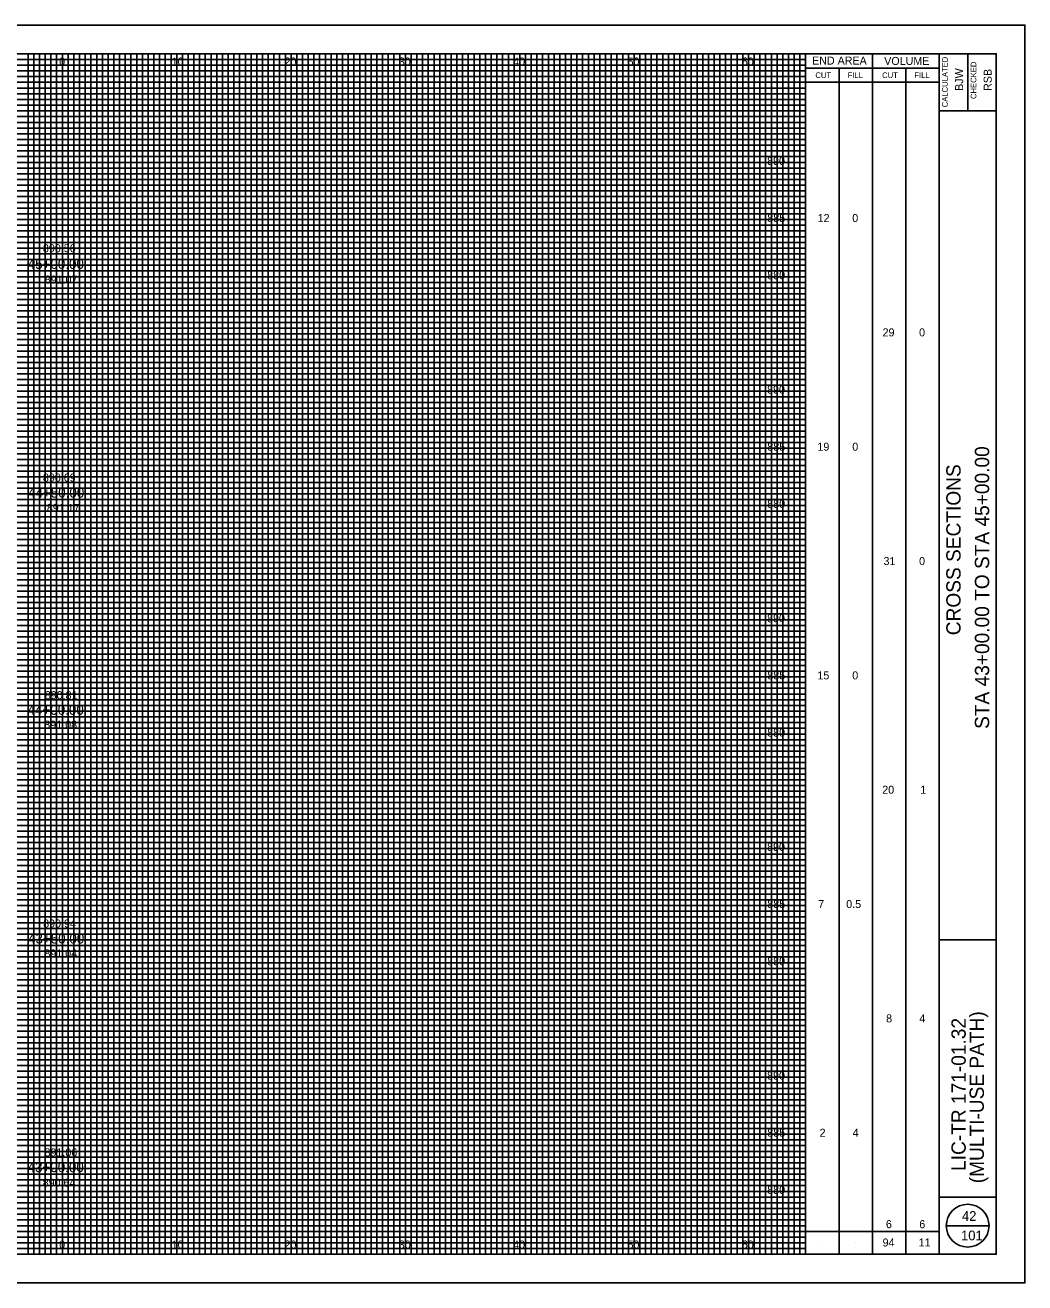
# Model space of a CAD drawing. Extents: x -10 to 160, y -2 to 2522.
# Drawn here: x 72.6 to 160, y 1607.5 to 1717.5 of the extents above; entities that cross this region are included whole.
import ezdxf

# ---------------------------------------------------------------- set-up
doc = ezdxf.new("R2010")
doc.units = 0
for name, color, linetype in [('GK_Cells', 7, 'Continuous'), ('GK_Patterns', 7, 'Continuous'), ('TX_P_10', 7, 'Continuous'), ('TX_X_10', 7, 'Continuous'), ('XS_P_Finished_Grade_Seeded', 7, 'Continuous'), ('XS_P_Pavt_Surface', 7, 'Continuous'), ('XS_P_Subgrade', 7, 'Continuous'), ('XS_X_Ground_Line', 7, 'Continuous')]:
    doc.layers.add(name, color=color, linetype=linetype)

msp = doc.modelspace()

# ---------------------------------------------------------------- linework, layer by layer
at = {"layer": 'GK_Cells'}
msp.add_lwpolyline([(-10, 1607.5), (160, 1607.5), (160, 1717.5), (-10, 1717.5)], close=True, dxfattribs=at)
at = {"layer": 'TX_P_10'}
for p, q in [((140.83, 1610), (140.83, 1715)), ((146.67, 1610), (146.67, 1715)), ((140.83, 1713.75), (152.5, 1713.75)), ((143.75, 1610), (143.75, 1713.75)), ((149.58, 1610), (149.58, 1713.75)), ((140.83, 1712.5), (152.5, 1712.5)), ((140.83, 1612), (152.5, 1612)), ((153.12, 1612.5), (156.88, 1612.5)), ((142.29, 1611), (142.29, 1611)), ((145.21, 1611), (145.21, 1611)), ((148.12, 1611), (148.12, 1611)), ((151.04, 1611), (151.04, 1611))]:
    msp.add_line(p, q, dxfattribs=at)
msp.add_circle((155, 1612.5), 1.87, dxfattribs=at)
at = {"layer": 'TX_X_10'}
for p, q in [((75.83, 1610), (75.83, 1715)), ((80.83, 1610), (80.83, 1715)), ((85.83, 1610), (85.83, 1715)), ((90.83, 1610), (90.83, 1715)), ((95.83, 1610), (95.83, 1715)), ((100.83, 1610), (100.83, 1715)), ((105.83, 1610), (105.83, 1715)), ((110.83, 1610), (110.83, 1715)), ((115.83, 1610), (115.83, 1715)), ((120.83, 1610), (120.83, 1715)), ((125.83, 1610), (125.83, 1715)), ((130.83, 1610), (130.83, 1715)), ((135.83, 1610), (135.83, 1715)), ((5.83, 1710), (140.83, 1710)), ((5.83, 1705), (140.83, 1705)), ((5.83, 1700), (140.83, 1700)), ((5.83, 1695), (140.83, 1695)), ((5.83, 1690), (140.83, 1690)), ((5.83, 1685), (140.83, 1685)), ((5.83, 1680), (140.83, 1680)), ((5.83, 1675), (140.83, 1675)), ((5.83, 1670), (140.83, 1670)), ((5.83, 1665), (140.83, 1665)), ((5.83, 1660), (140.83, 1660)), ((5.83, 1655), (140.83, 1655)), ((5.83, 1650), (140.83, 1650)), ((5.83, 1645), (140.83, 1645)), ((5.83, 1640), (140.83, 1640)), ((5.83, 1635), (140.83, 1635)), ((5.83, 1630), (140.83, 1630)), ((5.83, 1625), (140.83, 1625)), ((5.83, 1620), (140.83, 1620)), ((5.83, 1615), (140.83, 1615))]:
    msp.add_line(p, q, dxfattribs=at)
at = {"layer": 'XS_P_Pavt_Surface'}
for p, q in [((152.5, 1610), (152.5, 1715)), ((155, 1715), (155, 1710)), ((152.5, 1710), (157.5, 1710)), ((152.5, 1637.5), (157.5, 1637.5)), ((152.5, 1615), (157.5, 1615))]:
    msp.add_line(p, q, dxfattribs=at)
msp.add_lwpolyline([(0, 1715), (157.5, 1715), (157.5, 1610), (0, 1610)], close=True, dxfattribs=at)
at = {"layer": 'XS_X_Ground_Line'}
for p, q in [((72.83, 1610), (72.83, 1715)), ((73.33, 1610), (73.33, 1715)), ((73.83, 1610), (73.83, 1715)), ((74.33, 1610), (74.33, 1715)), ((74.83, 1610), (74.83, 1715)), ((75.33, 1610), (75.33, 1715)), ((76.33, 1610), (76.33, 1715)), ((76.83, 1610), (76.83, 1715)), ((77.33, 1610), (77.33, 1715)), ((77.83, 1610), (77.83, 1715)), ((78.33, 1610), (78.33, 1715)), ((78.83, 1610), (78.83, 1715)), ((79.33, 1610), (79.33, 1715)), ((79.83, 1610), (79.83, 1715)), ((80.33, 1610), (80.33, 1715)), ((81.33, 1610), (81.33, 1715)), ((81.83, 1610), (81.83, 1715)), ((82.33, 1610), (82.33, 1715)), ((82.83, 1610), (82.83, 1715)), ((83.33, 1610), (83.33, 1715)), ((83.83, 1610), (83.83, 1715)), ((84.33, 1610), (84.33, 1715)), ((84.83, 1610), (84.83, 1715)), ((85.33, 1610), (85.33, 1715)), ((86.33, 1610), (86.33, 1715)), ((86.83, 1610), (86.83, 1715)), ((87.33, 1610), (87.33, 1715)), ((87.83, 1610), (87.83, 1715)), ((88.33, 1610), (88.33, 1715)), ((88.83, 1610), (88.83, 1715)), ((89.33, 1610), (89.33, 1715)), ((89.83, 1610), (89.83, 1715)), ((90.33, 1610), (90.33, 1715)), ((91.33, 1610), (91.33, 1715)), ((91.83, 1610), (91.83, 1715)), ((92.33, 1610), (92.33, 1715)), ((92.83, 1610), (92.83, 1715)), ((93.33, 1610), (93.33, 1715)), ((93.83, 1610), (93.83, 1715)), ((94.33, 1610), (94.33, 1715)), ((94.83, 1610), (94.83, 1715)), ((95.33, 1610), (95.33, 1715)), ((96.33, 1610), (96.33, 1715)), ((96.83, 1610), (96.83, 1715)), ((97.33, 1610), (97.33, 1715)), ((97.83, 1610), (97.83, 1715)), ((98.33, 1610), (98.33, 1715)), ((98.83, 1610), (98.83, 1715)), ((99.33, 1610), (99.33, 1715)), ((99.83, 1610), (99.83, 1715)), ((100.33, 1610), (100.33, 1715)), ((101.33, 1610), (101.33, 1715)), ((101.83, 1610), (101.83, 1715)), ((102.33, 1610), (102.33, 1715)), ((102.83, 1610), (102.83, 1715)), ((103.33, 1610), (103.33, 1715)), ((103.83, 1610), (103.83, 1715)), ((104.33, 1610), (104.33, 1715)), ((104.83, 1610), (104.83, 1715)), ((105.33, 1610), (105.33, 1715)), ((106.33, 1610), (106.33, 1715)), ((106.83, 1610), (106.83, 1715)), ((107.33, 1610), (107.33, 1715)), ((107.83, 1610), (107.83, 1715)), ((108.33, 1610), (108.33, 1715)), ((108.83, 1610), (108.83, 1715)), ((109.33, 1610), (109.33, 1715)), ((109.83, 1610), (109.83, 1715)), ((110.33, 1610), (110.33, 1715)), ((111.33, 1610), (111.33, 1715)), ((111.83, 1610), (111.83, 1715)), ((112.33, 1610), (112.33, 1715)), ((112.83, 1610), (112.83, 1715)), ((113.33, 1610), (113.33, 1715)), ((113.83, 1610), (113.83, 1715)), ((114.33, 1610), (114.33, 1715)), ((114.83, 1610), (114.83, 1715)), ((115.33, 1610), (115.33, 1715)), ((116.33, 1610), (116.33, 1715)), ((116.83, 1610), (116.83, 1715)), ((117.33, 1610), (117.33, 1715)), ((117.83, 1610), (117.83, 1715)), ((118.33, 1610), (118.33, 1715)), ((118.83, 1610), (118.83, 1715)), ((119.33, 1610), (119.33, 1715)), ((119.83, 1610), (119.83, 1715)), ((120.33, 1610), (120.33, 1715)), ((121.33, 1610), (121.33, 1715)), ((121.83, 1610), (121.83, 1715)), ((122.33, 1610), (122.33, 1715)), ((122.83, 1610), (122.83, 1715)), ((123.33, 1610), (123.33, 1715)), ((123.83, 1610), (123.83, 1715)), ((124.33, 1610), (124.33, 1715)), ((124.83, 1610), (124.83, 1715)), ((125.33, 1610), (125.33, 1715)), ((126.33, 1610), (126.33, 1715)), ((126.83, 1610), (126.83, 1715)), ((127.33, 1610), (127.33, 1715)), ((127.83, 1610), (127.83, 1715)), ((128.33, 1610), (128.33, 1715)), ((128.83, 1610), (128.83, 1715)), ((129.33, 1610), (129.33, 1715)), ((129.83, 1610), (129.83, 1715)), ((130.33, 1610), (130.33, 1715)), ((131.33, 1610), (131.33, 1715)), ((131.83, 1610), (131.83, 1715)), ((132.33, 1610), (132.33, 1715)), ((132.83, 1610), (132.83, 1715)), ((133.33, 1610), (133.33, 1715)), ((133.83, 1610), (133.83, 1715)), ((134.33, 1610), (134.33, 1715)), ((134.83, 1610), (134.83, 1715)), ((135.33, 1610), (135.33, 1715)), ((136.33, 1610), (136.33, 1715)), ((136.83, 1610), (136.83, 1715)), ((137.33, 1610), (137.33, 1715)), ((137.83, 1610), (137.83, 1715)), ((138.33, 1610), (138.33, 1715)), ((138.83, 1610), (138.83, 1715)), ((139.33, 1610), (139.33, 1715)), ((139.83, 1610), (139.83, 1715)), ((140.33, 1610), (140.33, 1715)), ((5.83, 1714.5), (140.83, 1714.5)), ((5.83, 1714), (140.83, 1714)), ((5.83, 1713.5), (140.83, 1713.5)), ((5.83, 1713), (140.83, 1713)), ((5.83, 1712.5), (140.83, 1712.5)), ((5.83, 1712), (140.83, 1712)), ((5.83, 1711.5), (140.83, 1711.5)), ((5.83, 1711), (140.83, 1711)), ((5.83, 1710.5), (140.83, 1710.5)), ((5.83, 1709.5), (140.83, 1709.5)), ((5.83, 1709), (140.83, 1709)), ((5.83, 1708.5), (140.83, 1708.5)), ((5.83, 1708), (140.83, 1708)), ((5.83, 1707.5), (140.83, 1707.5)), ((5.83, 1707), (140.83, 1707)), ((5.83, 1706.5), (140.83, 1706.5)), ((5.83, 1706), (140.83, 1706)), ((5.83, 1705.5), (140.83, 1705.5)), ((5.83, 1704.5), (140.83, 1704.5)), ((5.83, 1704), (140.83, 1704)), ((5.83, 1703.5), (140.83, 1703.5)), ((5.83, 1703), (140.83, 1703)), ((5.83, 1702.5), (140.83, 1702.5)), ((5.83, 1702), (140.83, 1702)), ((5.83, 1701.5), (140.83, 1701.5)), ((5.83, 1701), (140.83, 1701)), ((5.83, 1700.5), (140.83, 1700.5)), ((5.83, 1699.5), (140.83, 1699.5)), ((5.83, 1699), (140.83, 1699)), ((5.83, 1698.5), (140.83, 1698.5)), ((5.83, 1698), (140.83, 1698)), ((5.83, 1697.5), (140.83, 1697.5)), ((5.83, 1697), (140.83, 1697)), ((5.83, 1696.5), (140.83, 1696.5)), ((5.83, 1696), (140.83, 1696)), ((5.83, 1695.5), (140.83, 1695.5)), ((5.83, 1694.5), (140.83, 1694.5)), ((5.83, 1694), (140.83, 1694)), ((5.83, 1693.5), (140.83, 1693.5)), ((5.83, 1693), (140.83, 1693)), ((5.83, 1692.5), (140.83, 1692.5)), ((5.83, 1692), (140.83, 1692)), ((5.83, 1691.5), (140.83, 1691.5)), ((5.83, 1691), (140.83, 1691)), ((5.83, 1690.5), (140.83, 1690.5)), ((5.83, 1689.5), (140.83, 1689.5)), ((5.83, 1689), (140.83, 1689)), ((5.83, 1688.5), (140.83, 1688.5)), ((5.83, 1688), (140.83, 1688)), ((5.83, 1687.5), (140.83, 1687.5)), ((5.83, 1687), (140.83, 1687)), ((5.83, 1686.5), (140.83, 1686.5)), ((5.83, 1686), (140.83, 1686)), ((5.83, 1685.5), (140.83, 1685.5)), ((5.83, 1684.5), (140.83, 1684.5)), ((5.83, 1684), (140.83, 1684)), ((5.83, 1683.5), (140.83, 1683.5)), ((5.83, 1683), (140.83, 1683)), ((5.83, 1682.5), (140.83, 1682.5)), ((5.83, 1682), (140.83, 1682)), ((5.83, 1681.5), (140.83, 1681.5)), ((5.83, 1681), (140.83, 1681)), ((5.83, 1680.5), (140.83, 1680.5)), ((5.83, 1679.5), (140.83, 1679.5)), ((5.83, 1679), (140.83, 1679)), ((5.83, 1678.5), (140.83, 1678.5)), ((5.83, 1678), (140.83, 1678)), ((5.83, 1677.5), (140.83, 1677.5)), ((5.83, 1677), (140.83, 1677)), ((5.83, 1676.5), (140.83, 1676.5)), ((5.83, 1676), (140.83, 1676)), ((5.83, 1675.5), (140.83, 1675.5)), ((5.83, 1674.5), (140.83, 1674.5)), ((5.83, 1674), (140.83, 1674)), ((5.83, 1673.5), (140.83, 1673.5)), ((5.83, 1673), (140.83, 1673)), ((5.83, 1672.5), (140.83, 1672.5)), ((5.83, 1672), (140.83, 1672)), ((5.83, 1671.5), (140.83, 1671.5)), ((5.83, 1671), (140.83, 1671)), ((5.83, 1670.5), (140.83, 1670.5)), ((5.83, 1669.5), (140.83, 1669.5)), ((5.83, 1669), (140.83, 1669)), ((5.83, 1668.5), (140.83, 1668.5)), ((5.83, 1668), (140.83, 1668)), ((5.83, 1667.5), (140.83, 1667.5)), ((5.83, 1667), (140.83, 1667)), ((5.83, 1666.5), (140.83, 1666.5)), ((5.83, 1666), (140.83, 1666)), ((5.83, 1665.5), (140.83, 1665.5)), ((5.83, 1664.5), (140.83, 1664.5)), ((5.83, 1664), (140.83, 1664)), ((5.83, 1663.5), (140.83, 1663.5)), ((5.83, 1663), (140.83, 1663)), ((5.83, 1662.5), (140.83, 1662.5)), ((5.83, 1662), (140.83, 1662)), ((5.83, 1661.5), (140.83, 1661.5)), ((5.83, 1661), (140.83, 1661)), ((5.83, 1660.5), (140.83, 1660.5)), ((5.83, 1659.5), (140.83, 1659.5)), ((5.83, 1659), (140.83, 1659)), ((5.83, 1658.5), (140.83, 1658.5)), ((5.83, 1658), (140.83, 1658)), ((5.83, 1657.5), (140.83, 1657.5)), ((5.83, 1657), (140.83, 1657)), ((5.83, 1656.5), (140.83, 1656.5)), ((5.83, 1656), (140.83, 1656)), ((5.83, 1655.5), (140.83, 1655.5)), ((5.83, 1654.5), (140.83, 1654.5)), ((5.83, 1654), (140.83, 1654)), ((5.83, 1653.5), (140.83, 1653.5)), ((5.83, 1653), (140.83, 1653)), ((5.83, 1652.5), (140.83, 1652.5)), ((5.83, 1652), (140.83, 1652)), ((5.83, 1651.5), (140.83, 1651.5)), ((5.83, 1651), (140.83, 1651)), ((5.83, 1650.5), (140.83, 1650.5)), ((5.83, 1649.5), (140.83, 1649.5)), ((5.83, 1649), (140.83, 1649)), ((5.83, 1648.5), (140.83, 1648.5)), ((5.83, 1648), (140.83, 1648)), ((5.83, 1647.5), (140.83, 1647.5)), ((5.83, 1647), (140.83, 1647)), ((5.83, 1646.5), (140.83, 1646.5)), ((5.83, 1646), (140.83, 1646)), ((5.83, 1645.5), (140.83, 1645.5)), ((5.83, 1644.5), (140.83, 1644.5)), ((5.83, 1644), (140.83, 1644)), ((5.83, 1643.5), (140.83, 1643.5)), ((5.83, 1643), (140.83, 1643)), ((5.83, 1642.5), (140.83, 1642.5)), ((5.83, 1642), (140.83, 1642)), ((5.83, 1641.5), (140.83, 1641.5)), ((5.83, 1641), (140.83, 1641)), ((5.83, 1640.5), (140.83, 1640.5)), ((5.83, 1639.5), (140.83, 1639.5)), ((5.83, 1639), (140.83, 1639)), ((5.83, 1638.5), (140.83, 1638.5)), ((5.83, 1638), (140.83, 1638)), ((5.83, 1637.5), (140.83, 1637.5)), ((5.83, 1637), (140.83, 1637)), ((5.83, 1636.5), (140.83, 1636.5)), ((5.83, 1636), (140.83, 1636)), ((5.83, 1635.5), (140.83, 1635.5)), ((5.83, 1634.5), (140.83, 1634.5)), ((5.83, 1634), (140.83, 1634)), ((5.83, 1633.5), (140.83, 1633.5)), ((5.83, 1633), (140.83, 1633)), ((5.83, 1632.5), (140.83, 1632.5)), ((5.83, 1632), (140.83, 1632)), ((5.83, 1631.5), (140.83, 1631.5)), ((5.83, 1631), (140.83, 1631)), ((5.83, 1630.5), (140.83, 1630.5)), ((5.83, 1629.5), (140.83, 1629.5)), ((5.83, 1629), (140.83, 1629)), ((5.83, 1628.5), (140.83, 1628.5)), ((5.83, 1628), (140.83, 1628)), ((5.83, 1627.5), (140.83, 1627.5)), ((5.83, 1627), (140.83, 1627)), ((5.83, 1626.5), (140.83, 1626.5)), ((5.83, 1626), (140.83, 1626)), ((5.83, 1625.5), (140.83, 1625.5)), ((5.83, 1624.5), (140.83, 1624.5)), ((5.83, 1624), (140.83, 1624)), ((5.83, 1623.5), (140.83, 1623.5)), ((5.83, 1623), (140.83, 1623)), ((5.83, 1622.5), (140.83, 1622.5)), ((5.83, 1622), (140.83, 1622)), ((5.83, 1621.5), (140.83, 1621.5)), ((5.83, 1621), (140.83, 1621)), ((5.83, 1620.5), (140.83, 1620.5)), ((5.83, 1619.5), (140.83, 1619.5)), ((5.83, 1619), (140.83, 1619)), ((5.83, 1618.5), (140.83, 1618.5)), ((5.83, 1618), (140.83, 1618)), ((5.83, 1617.5), (140.83, 1617.5)), ((5.83, 1617), (140.83, 1617)), ((5.83, 1616.5), (140.83, 1616.5)), ((5.83, 1616), (140.83, 1616)), ((5.83, 1615.5), (140.83, 1615.5)), ((5.83, 1614.5), (140.83, 1614.5)), ((5.83, 1614), (140.83, 1614)), ((5.83, 1613.5), (140.83, 1613.5)), ((5.83, 1613), (140.83, 1613)), ((5.83, 1612.5), (140.83, 1612.5)), ((5.83, 1612), (140.83, 1612)), ((5.83, 1611.5), (140.83, 1611.5)), ((5.83, 1611), (140.83, 1611)), ((5.83, 1610.5), (140.83, 1610.5))]:
    msp.add_line(p, q, dxfattribs=at)

# ---------------------------------------------------------------- texts
at = {"layer": 'GK_Patterns'}
for s, height, p in [('0', 0.7, (75.55, 1713.97)), ('0', 0.7, (75.55, 1713.97)), ('10', 0.7, (85.39, 1713.97)), ('20', 0.7, (95.26, 1713.97)), ('30', 0.7, (105.25, 1713.97)), ('40', 0.7, (115.25, 1713.97)), ('50', 0.7, (125.25, 1713.97)), ('60', 0.7, (135.25, 1713.97)), ('890', 0.7, (137.46, 1705.28)), ('885', 0.7, (137.48, 1700.28)), ('12', 0.7, (141.88, 1700.28)), ('0', 0.7, (144.91, 1700.28)), ('45+00.00', 0.875, (72.8, 1696.18)), ('880', 0.7, (137.47, 1695.28)), ('29', 0.7, (147.56, 1690.28)), ('0', 0.7, (150.75, 1690.28)), ('890', 0.7, (137.46, 1685.28)), ('885', 0.7, (137.48, 1680.28)), ('19', 0.7, (141.86, 1680.28)), ('0', 0.7, (144.91, 1680.28)), ('44+50.00', 0.875, (72.83, 1676.18)), ('880', 0.7, (137.47, 1675.28)), ('31', 0.7, (147.64, 1670.28)), ('0', 0.7, (150.75, 1670.28)), ('890', 0.7, (137.46, 1665.28)), ('885', 0.7, (137.48, 1660.28)), ('15', 0.7, (141.86, 1660.28)), ('0', 0.7, (144.91, 1660.28)), ('44+00.00', 0.875, (72.79, 1657.18)), ('880', 0.7, (137.47, 1655.28)), ('20', 0.7, (147.53, 1650.28)), ('1', 0.7, (150.86, 1650.28)), ('890', 0.7, (137.46, 1645.28)), ('885', 0.7, (137.48, 1640.28)), ('7', 0.7, (141.93, 1640.28)), ('0.5', 0.7, (144.38, 1640.28)), ('43+50.00', 0.875, (72.83, 1637.18)), ('880', 0.7, (137.47, 1635.28)), ('8', 0.7, (147.87, 1630.28)), ('4', 0.7, (150.77, 1630.28)), ('890', 0.7, (137.46, 1625.28)), ('885', 0.7, (137.48, 1620.28)), ('2', 0.7, (142.05, 1620.28)), ('4', 0.7, (144.94, 1620.28)), ('43+00.00', 0.875, (72.79, 1617.18)), ('880', 0.7, (137.47, 1615.28)), ('6', 0.7, (147.85, 1612.28)), ('6', 0.7, (150.77, 1612.28)), ('0', 0.7, (75.55, 1610.5)), ('0', 0.7, (75.55, 1610.5)), ('10', 0.7, (85.39, 1610.5)), ('20', 0.7, (95.26, 1610.5)), ('30', 0.7, (105.25, 1610.5)), ('40', 0.7, (115.25, 1610.5)), ('50', 0.7, (125.25, 1610.5)), ('60', 0.7, (135.25, 1610.5)), ('94', 0.7, (147.56, 1610.68)), ('11', 0.7, (150.71, 1610.68))]:
    msp.add_text(s, height=height, dxfattribs=at).set_placement(p)
at = {"layer": 'TX_P_10'}
for s, height, p in [('END AREA', 0.7, (141.39, 1714.05)), ('VOLUME', 0.7, (147.7, 1714.02)), ('CUT', 0.5, (141.68, 1712.87)), ('FILL', 0.5, (144.5, 1712.87)), ('CUT', 0.5, (147.52, 1712.87)), ('FILL', 0.5, (150.34, 1712.87)), ('42', 0.85, (154.5, 1612.92)), ('101', 0.85, (154.42, 1611.22))]:
    msp.add_text(s, height=height, dxfattribs=at).set_placement(p)
for s, height, p in [('CALCULATED', 0.5, (153.26, 1710.32)), ('CHECKED', 0.5, (155.76, 1711.04)), ('BJW', 0.7, (154.6, 1711.75)), ('RSB', 0.7, (157.1, 1711.75)), ('STA 43+00.00 TO STA 45+00.00', 1.25, (156.88, 1655.95)), ('CROSS SECTIONS', 1.25, (154.38, 1664.14)), ('LIC-TR 171-01.32', 1.25, (154.83, 1617.29)), ('(MULTI-USE PATH)', 1.25, (156.42, 1616.21))]:
    msp.add_text(s, height=height, rotation=90, dxfattribs=at).set_placement(p)
at = {"layer": 'XS_P_Finished_Grade_Seeded'}
for s, p in [('891.07', (74.29, 1694.9)), ('891.17', (74.47, 1674.93)), ('891.08', (74.25, 1655.97)), ('891.04', (74.26, 1635.96)), ('890.64', (74.11, 1615.91))]:
    msp.add_text(s, height=0.7, dxfattribs=at).set_placement(p)
at = {"layer": 'XS_P_Subgrade'}
for s, p in [('890.56', (74.13, 1697.64)), ('890.69', (74.13, 1677.58)), ('890.81', (74.29, 1658.55)), ('890.94', (74.15, 1638.58)), ('891.06', (74.27, 1618.56))]:
    msp.add_text(s, height=0.7, dxfattribs=at).set_placement(p)

doc.saveas('drawing.dxf')
